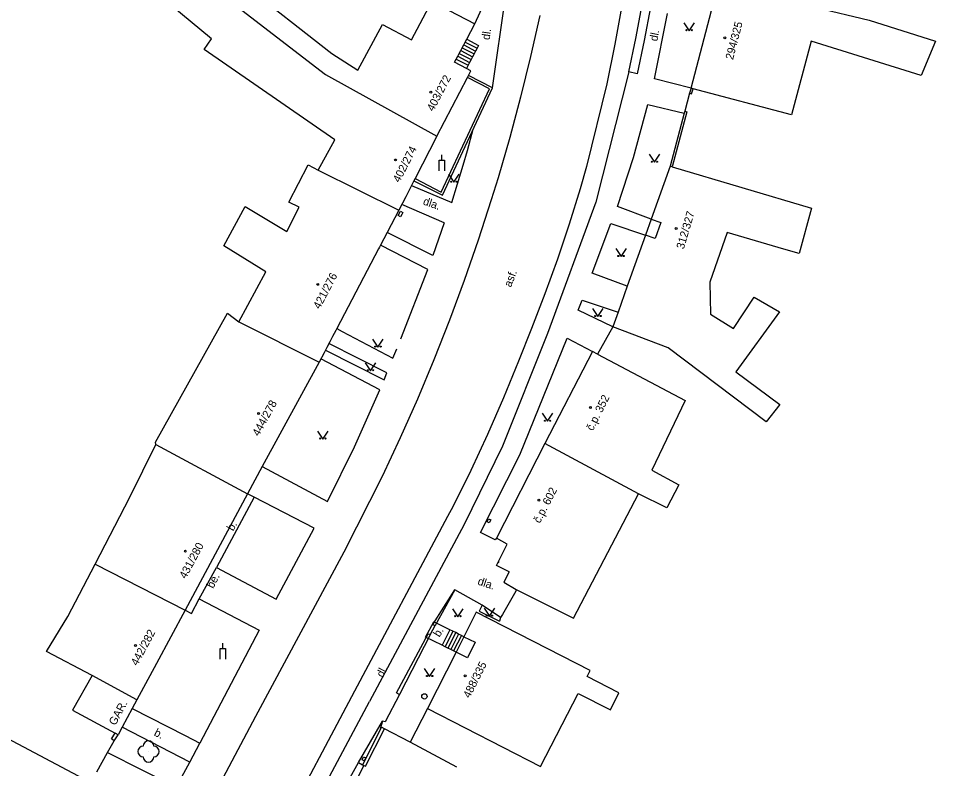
# Model space of a CAD drawing. Extents: x -577457 to -568404, y -1208466 to -1201387.
# Drawn here: x -568911.7 to -568825.8, y -1204266 to -1204195.7 of the extents above; entities that cross this region are included whole.
import ezdxf

# ---------------------------------------------------------------- set-up
doc = ezdxf.new("R2010")
doc.units = 0
for name, color, linetype in [('BUDOVY_MĚŘ', 7, 'Continuous'), ('BUDOVY_NEMĚŘ', 7, 'Continuous'), ('OBVOD_PILÍŘE', 7, 'Continuous'), ('POMOC_POPIS', 7, 'Continuous'), ('ROZHRANÍ_PLOCH', 7, 'Continuous'), ('ZELEŇ', 7, 'Continuous'), ('ZN_BUDOV', 7, 'Continuous'), ('ZN_DOPLŇKOVÉ', 7, 'Continuous'), ('ZN_KULTUR', 7, 'Continuous'), ('Č_POPIS_ORIENT', 7, 'Continuous')]:
    doc.layers.add(name, color=color, linetype=linetype)

msp = doc.modelspace()

# ---------------------------------------------------------------- linework, layer by layer
at = {"layer": 'BUDOVY_MĚŘ'}
for points in [[(-568848.71, -1204202.25), (-568846.12, -1204192.3)], [(-568869.73, -1204197.65), (-568868.98, -1204196.22)], [(-568870, -1204198.18), (-568869.86, -1204197.91)], [(-568869.86, -1204197.91), (-568869.73, -1204197.65)], [(-568870.56, -1204199.24), (-568870.42, -1204198.98)], [(-568870.42, -1204198.98), (-568870.28, -1204198.71)], [(-568870.28, -1204198.71), (-568870.14, -1204198.45)], [(-568870.14, -1204198.45), (-568870, -1204198.18)], [(-568869.74, -1204200.4), (-568870.86, -1204199.81), (-568870.7, -1204199.51)], [(-568870.7, -1204199.51), (-568870.56, -1204199.24)], [(-568869.56, -1204201.04), (-568869.33, -1204200.61), (-568869.74, -1204200.4)], [(-568872.53, -1204206.74), (-568869.66, -1204201.24)], [(-568869.66, -1204201.24), (-568869.56, -1204201.04)], [(-568848.52, -1204202.3), (-568848.71, -1204202.25)], [(-568872.53, -1204206.74), (-568874.57, -1204210.72)], [(-568850.66, -1204209.54), (-568852.44, -1204214.51)], [(-568850.47, -1204209.61), (-568850.66, -1204209.54)], [(-568874.67, -1204210.92), (-568874.9, -1204211.36)], [(-568874.57, -1204210.72), (-568874.67, -1204210.92)], [(-568874.9, -1204211.36), (-568875.43, -1204212.41)], [(-568875.43, -1204212.41), (-568876.09, -1204213.69)], [(-568876.09, -1204213.69), (-568877.18, -1204215.76)], [(-568852.44, -1204214.51), (-568852.97, -1204216.01)], [(-568852.44, -1204214.51), (-568851.54, -1204214.83), (-568852.08, -1204216.33), (-568852.97, -1204216.01)], [(-568877.18, -1204215.76), (-568877.81, -1204216.96)], [(-568852.97, -1204216.01), (-568854.68, -1204220.81)], [(-568877.81, -1204216.96), (-568877.9, -1204217.13)], [(-568877.99, -1204217.31), (-568881.9, -1204224.78)], [(-568877.9, -1204217.13), (-568877.99, -1204217.31)], [(-568854.68, -1204220.81), (-568855.55, -1204223.25)], [(-568855.55, -1204223.25), (-568856.04, -1204224.61)], [(-568881.9, -1204224.78), (-568881.99, -1204224.95)], [(-568882.29, -1204225.51), (-568882.56, -1204226.03)], [(-568881.99, -1204224.95), (-568882.29, -1204225.51)], [(-568882.56, -1204226.03), (-568882.82, -1204226.54)], [(-568883.09, -1204227.05), (-568883.55, -1204227.92)], [(-568882.82, -1204226.54), (-568883.09, -1204227.05)], [(-568857.93, -1204226.94), (-568862.4, -1204235.55)], [(-568857.48, -1204227.16), (-568857.93, -1204226.94)], [(-568883.55, -1204227.92), (-568888.88, -1204237.7)], [(-568862.4, -1204235.55), (-568866.94, -1204244.43)], [(-568888.88, -1204237.7), (-568890.27, -1204240.26)], [(-568890.27, -1204240.26), (-568896.11, -1204251.18)], [(-568865.94, -1204244.99), (-568866.94, -1204244.43)], [(-568866.95, -1204246.98), (-568865.94, -1204244.99)], [(-568865.75, -1204247.58), (-568866.95, -1204246.98)], [(-568866.72, -1204246.65), (-568866.78, -1204246.77)], [(-568865.75, -1204247.58), (-568866.24, -1204248.55)], [(-568866.24, -1204248.55), (-568865.08, -1204249.24)], [(-568896.11, -1204251.18), (-568898.79, -1204256.16)], [(-568868.84, -1204251.35), (-568870, -1204253.66)], [(-568870, -1204253.66), (-568868.93, -1204254.19), (-568869.65, -1204255.64), (-568870.73, -1204255.1)], [(-568870, -1204253.66), (-568870.73, -1204255.1)], [(-568870.73, -1204255.1), (-568873.39, -1204260.4)], [(-568898.79, -1204256.16), (-568900.63, -1204259.59)], [(-568900.63, -1204259.59), (-568901.07, -1204260.4)], [(-568901.07, -1204260.4), (-568902.01, -1204262.15)], [(-568902.01, -1204262.15), (-568902.39, -1204262.86)], [(-568902.39, -1204262.86), (-568902.65, -1204262.72)]]:
    msp.add_lwpolyline(points, dxfattribs=at)
at = {"layer": 'BUDOVY_NEMĚŘ'}
for points in [[(-568883.64, -1204209.91), (-568882.08, -1204207.07), (-568894.33, -1204198.62), (-568893.64, -1204197.62), (-568905.07, -1204188.12), (-568902.99, -1204185.45), (-568896.69, -1204190.35), (-568892.01, -1204194), (-568882.96, -1204200.94), (-568872.53, -1204206.74)], [(-568892.01, -1204194), (-568890.82, -1204192.33), (-568882.37, -1204198.99), (-568879.93, -1204200.55), (-568877.61, -1204196.28), (-568874.91, -1204197.7), (-568873.01, -1204194.12), (-568868.98, -1204196.22)], [(-568836.99, -1204194.68), (-568832.03, -1204195.87), (-568825.79, -1204197.84), (-568827.15, -1204201.06), (-568837.45, -1204197.83), (-568839.31, -1204204.74), (-568848.52, -1204202.3)], [(-568891.08, -1204224.13), (-568888.56, -1204219.47), (-568892.49, -1204217.03), (-568890.47, -1204213.33), (-568886.58, -1204215.68), (-568885.43, -1204213.4), (-568886.38, -1204212.91), (-568884.58, -1204209.42), (-568883.64, -1204209.91), (-568876.09, -1204213.69)], [(-568850.47, -1204209.61), (-568837.41, -1204213.5), (-568838.58, -1204217.74), (-568840, -1204217.32), (-568845.32, -1204215.76), (-568846.96, -1204220.41), (-568846.87, -1204223.42), (-568844.73, -1204224.77), (-568842.79, -1204221.83), (-568840.43, -1204223.21), (-568844.52, -1204228.83), (-568840.39, -1204231.89), (-568841.66, -1204233.53), (-568850.84, -1204226.59), (-568856.04, -1204224.61)], [(-568898.85, -1204235.64), (-568898.87, -1204235.42), (-568892.14, -1204223.32), (-568891.08, -1204224.13), (-568883.55, -1204227.92)], [(-568857.48, -1204227.16), (-568849.26, -1204231.52), (-568852.37, -1204238.06), (-568849.84, -1204239.43), (-568850.98, -1204241.59), (-568853.64, -1204240.28)], [(-568904.54, -1204246.87), (-568901.28, -1204240.58), (-568898.85, -1204235.64), (-568890.27, -1204240.26)], [(-568853.64, -1204240.28), (-568862.4, -1204235.55)], [(-568859.72, -1204251.94), (-568853.64, -1204240.28)], [(-568904.83, -1204257.31), (-568909.1, -1204255.04), (-568907.09, -1204251.77), (-568904.54, -1204246.87), (-568896.11, -1204251.18)], [(-568865.08, -1204249.24), (-568859.72, -1204251.94)], [(-568873.39, -1204260.4), (-568862.8, -1204265.84), (-568859.27, -1204258.99), (-568856.27, -1204260.53), (-568855.47, -1204258.94), (-568858.45, -1204257.4), (-568858.15, -1204256.83), (-568868.84, -1204251.35)], [(-568900.63, -1204259.59), (-568904.83, -1204257.31), (-568906.67, -1204260.55), (-568902.65, -1204262.72)], [(-568919.63, -1204274.47), (-568913.32, -1204262.9), (-568905.13, -1204267.24)]]:
    msp.add_lwpolyline(points, dxfattribs=at)
at = {"layer": 'OBVOD_PILÍŘE'}
for points in [[(-568875.82, -1204214.09), (-568875.93, -1204214.3), (-568876.15, -1204214.18), (-568875.93, -1204213.77), (-568875.71, -1204213.88), (-568875.82, -1204214.09)], [(-568867.74, -1204242.74), (-568867.67, -1204242.6), (-568867.47, -1204242.7), (-568867.62, -1204242.98), (-568867.81, -1204242.88), (-568867.74, -1204242.74)], [(-568879.46, -1204265.06), (-568879.39, -1204264.92), (-568879.19, -1204265.02), (-568879.34, -1204265.3), (-568879.53, -1204265.2), (-568879.46, -1204265.06)]]:
    msp.add_lwpolyline(points, dxfattribs=at)
at = {"layer": 'ROZHRANÍ_PLOCH'}
for points in [[(-568852.84, -1204191.52), (-568851.72, -1204182.22), (-568850.93, -1204182.32), (-568852.05, -1204191.64), (-568852.52, -1204194.63), (-568853.1, -1204197.76), (-568853.75, -1204200.88), (-568854.53, -1204200.71), (-568853.88, -1204197.58), (-568853.3, -1204194.43), (-568852.84, -1204191.52)], [(-568867.3, -1204202.19), (-568866.1, -1204193.68)], [(-568855.15, -1204194.34), (-568855.84, -1204198.1)], [(-568862.89, -1204195.42), (-568863.75, -1204199.26)], [(-568852.14, -1204201.36), (-568850.92, -1204195.24)], [(-568869.86, -1204197.91), (-568868.75, -1204198.5)], [(-568869.73, -1204197.65), (-568868.61, -1204198.23), (-568868.75, -1204198.5)], [(-568855.84, -1204198.1), (-568856.61, -1204201.84)], [(-568870.42, -1204198.98), (-568869.31, -1204199.56)], [(-568870.28, -1204198.71), (-568869.17, -1204199.29)], [(-568870.14, -1204198.45), (-568869.03, -1204199.03)], [(-568870, -1204198.18), (-568868.89, -1204198.76)], [(-568868.89, -1204198.76), (-568869.03, -1204199.03)], [(-568868.75, -1204198.5), (-568868.89, -1204198.76)], [(-568870.7, -1204199.51), (-568869.58, -1204200.09)], [(-568870.56, -1204199.24), (-568869.45, -1204199.83)], [(-568869.45, -1204199.83), (-568869.58, -1204200.09)], [(-568869.31, -1204199.56), (-568869.45, -1204199.83)], [(-568869.17, -1204199.29), (-568869.31, -1204199.56)], [(-568869.03, -1204199.03), (-568869.17, -1204199.29)], [(-568863.75, -1204199.26), (-568864.68, -1204203.07)], [(-568869.58, -1204200.09), (-568869.74, -1204200.4)], [(-568854.53, -1204200.71), (-568857.63, -1204212.94)], [(-568848.71, -1204202.25), (-568852.14, -1204201.36)], [(-568856.61, -1204201.84), (-568858.49, -1204209.59)], [(-568864.68, -1204203.07), (-568865.69, -1204206.87)], [(-568852.44, -1204214.51), (-568855.61, -1204213.34), (-568854.11, -1204208.74), (-568852.75, -1204203.77), (-568849.34, -1204204.59)], [(-568869.65, -1204208.08), (-568869.12, -1204206.09)], [(-568865.69, -1204206.87), (-568866.78, -1204210.64)], [(-568870.05, -1204209.47), (-568869.65, -1204208.08)], [(-568871.12, -1204212.97), (-568870.05, -1204209.47)], [(-568858.49, -1204209.59), (-568859.09, -1204211.66)], [(-568866.78, -1204210.64), (-568867.42, -1204212.7)], [(-568874.9, -1204211.36), (-568871.12, -1204212.97)], [(-568859.09, -1204211.66), (-568860.12, -1204214.98)], [(-568867.42, -1204212.7), (-568868.65, -1204216.49)], [(-568871.83, -1204214.87), (-568875.8, -1204213.13)], [(-568857.63, -1204212.94), (-568862.15, -1204225.24)], [(-568871.83, -1204214.87), (-568872.9, -1204217.93)], [(-568860.12, -1204214.98), (-568861.22, -1204218.27)], [(-568854.68, -1204220.81), (-568857.97, -1204219.59), (-568856.21, -1204214.91), (-568852.97, -1204216.01)], [(-568872.9, -1204217.93), (-568877.18, -1204215.76)], [(-568873.36, -1204219.25), (-568877.81, -1204216.96)], [(-568868.65, -1204216.49), (-568869.97, -1204220.26)], [(-568861.22, -1204218.27), (-568862.4, -1204221.53)], [(-568875.91, -1204225.73), (-568873.36, -1204219.25)], [(-568869.97, -1204220.26), (-568871.35, -1204223.99)], [(-568862.4, -1204221.53), (-568863.66, -1204224.77)], [(-568856.04, -1204224.61), (-568859.29, -1204223.04), (-568858.92, -1204222.1), (-568855.55, -1204223.25)], [(-568881.9, -1204224.78), (-568881.4, -1204225.04)], [(-568871.35, -1204223.99), (-568872.81, -1204227.7)], [(-568863.66, -1204224.77), (-568864.86, -1204227.84)], [(-568881.4, -1204225.04), (-568876.65, -1204227.55)], [(-568862.15, -1204225.24), (-568866.38, -1204235.81)], [(-568877.2, -1204228.93), (-568882.64, -1204226.19)], [(-568864.76, -1204236.6), (-568860.33, -1204225.66)], [(-568860.33, -1204225.66), (-568857.93, -1204226.94)], [(-568882.96, -1204226.81), (-568877.47, -1204229.59)], [(-568876.65, -1204227.55), (-568876.28, -1204226.68)], [(-568877.87, -1204230.52), (-568883.39, -1204227.62)], [(-568872.81, -1204227.7), (-568874.35, -1204231.38)], [(-568864.86, -1204227.84), (-568866.28, -1204231.28)], [(-568877.47, -1204229.59), (-568877.2, -1204228.93)], [(-568880.25, -1204235.87), (-568877.87, -1204230.52)], [(-568874.35, -1204231.38), (-568875.96, -1204235.03)], [(-568866.28, -1204231.28), (-568867.78, -1204234.7)], [(-568875.96, -1204235.03), (-568877.64, -1204238.64)], [(-568867.78, -1204234.7), (-568869.35, -1204238.08)], [(-568882.76, -1204240.99), (-568880.25, -1204235.87)], [(-568866.38, -1204235.81), (-568869.98, -1204243.15)], [(-568868.45, -1204243.9), (-568864.76, -1204236.6)], [(-568888.88, -1204237.7), (-568882.76, -1204240.99)], [(-568869.35, -1204238.08), (-568870.99, -1204241.42)], [(-568877.64, -1204238.64), (-568881.23, -1204245.73)], [(-568893.17, -1204247.16), (-568887.57, -1204250.14), (-568884.02, -1204243.49), (-568889.65, -1204240.58)], [(-568889.65, -1204240.58), (-568893.17, -1204247.16)], [(-568889.65, -1204240.58), (-568890.27, -1204240.26)], [(-568870.99, -1204241.42), (-568871.54, -1204242.39)], [(-568871.54, -1204242.39), (-568880.24, -1204258.77)], [(-568869.98, -1204243.15), (-568878.83, -1204259.75)], [(-568867.05, -1204244.58), (-568868.45, -1204243.9)], [(-568866.94, -1204244.43), (-568867.05, -1204244.58)], [(-568881.23, -1204245.73), (-568889.51, -1204261.16)], [(-568894.79, -1204250.12), (-568893.17, -1204247.16)], [(-568872.89, -1204252.51), (-568870.83, -1204249.28)], [(-568896.11, -1204251.18), (-568895.51, -1204251.49), (-568894.79, -1204250.12)], [(-568894.79, -1204250.12), (-568889.16, -1204253.06), (-568894.74, -1204263.63)], [(-568866.55, -1204251.86), (-568868.27, -1204250.71)], [(-568873.6, -1204253.7), (-568872.82, -1204252.26)], [(-568871.3, -1204253.01), (-568872.82, -1204252.26)], [(-568872.89, -1204252.51), (-568872.68, -1204252.62)], [(-568871.3, -1204253.01), (-568872.03, -1204254.47)], [(-568871.03, -1204253.15), (-568871.3, -1204253.01)], [(-568876.31, -1204258.93), (-568873.34, -1204253.39)], [(-568872.03, -1204254.47), (-568873.6, -1204253.7)], [(-568873.34, -1204253.39), (-568873.12, -1204253.42)], [(-568871.03, -1204253.15), (-568871.76, -1204254.6)], [(-568870.76, -1204253.28), (-568871.49, -1204254.73)], [(-568870.49, -1204253.41), (-568871.22, -1204254.86)], [(-568870.76, -1204253.28), (-568871.03, -1204253.15)], [(-568870.22, -1204253.55), (-568870.95, -1204254.99)], [(-568870.49, -1204253.41), (-568870.76, -1204253.28)], [(-568870.22, -1204253.55), (-568870.49, -1204253.41)], [(-568870, -1204253.66), (-568870.22, -1204253.55)], [(-568871.76, -1204254.6), (-568872.03, -1204254.47)], [(-568871.49, -1204254.73), (-568871.76, -1204254.6)], [(-568871.22, -1204254.86), (-568871.49, -1204254.73)], [(-568870.95, -1204254.99), (-568871.22, -1204254.86)], [(-568870.73, -1204255.1), (-568870.95, -1204254.99)], [(-568880.24, -1204258.77), (-568894.54, -1204285.77)], [(-568876.31, -1204258.93), (-568876.01, -1204259.09)], [(-568893.08, -1204286.46), (-568878.83, -1204259.75)], [(-568901.07, -1204260.4), (-568896.12, -1204262.93), (-568894.74, -1204263.63)], [(-568889.51, -1204261.16), (-568901.2, -1204283.21)], [(-568879.86, -1204265.46), (-568877.63, -1204261.58)], [(-568877.37, -1204261.66), (-568877.63, -1204261.58)], [(-568895.67, -1204265.43), (-568902.01, -1204262.15)], [(-568895.67, -1204265.43), (-568894.74, -1204263.63)], [(-568903.37, -1204264.51), (-568896.96, -1204267.78), (-568895.67, -1204265.43)], [(-568882.47, -1204270.1), (-568879.86, -1204265.46)], [(-568879.86, -1204265.46), (-568879.49, -1204265.67)]]:
    msp.add_lwpolyline(points, dxfattribs=at)
at = {"layer": 'ZELEŇ'}
msp.add_circle((-568899.54, -1204264.43), 0.0005, dxfattribs=at)
for centre, start, end in [((-568899.54, -1204263.93), 0, 179.99999), ((-568900.04, -1204264.43), 89.99999, 269.99999), ((-568899.04, -1204264.43), 270, 89.99999), ((-568899.54, -1204264.93), 179.99999, 359.99999)]:
    msp.add_arc(centre, 0.5, start, end, dxfattribs=at)
at = {"layer": 'ZN_BUDOV'}
for centre in [(-568845.54, -1204197.51), (-568873.08, -1204202.62), (-568876.39, -1204208.97), (-568850.1, -1204215.39), (-568883.69, -1204220.63), (-568858.14, -1204232.18), (-568889.22, -1204232.73), (-568862.96, -1204240.86), (-568896.09, -1204245.65), (-568900.76, -1204254.48), (-568869.88, -1204257.34)]:
    msp.add_circle(centre, 0.0875, dxfattribs=at)
at = {"layer": 'ZN_DOPLŇKOVÉ'}
for p, q in [((-568872.05, -1204208.98), (-568872.05, -1204208.48)), ((-568892.57, -1204254.78), (-568892.57, -1204254.28))]:
    msp.add_line(p, q, dxfattribs=at)
for points in [[(-568868.98, -1204196.22), (-568867.77, -1204193.57)], [(-568874.57, -1204210.72), (-568872.11, -1204211.98), (-568867.59, -1204202.29), (-568869.66, -1204201.24)], [(-568867.3, -1204202.19), (-568869.56, -1204201.04)], [(-568874.67, -1204210.92), (-568872.01, -1204212.28), (-568867.3, -1204202.19)], [(-568848.71, -1204202.25), (-568848.85, -1204202.72)], [(-568848.85, -1204202.72), (-568848.66, -1204202.78), (-568848.52, -1204202.3)], [(-568848.85, -1204202.72), (-568849.29, -1204204.4)], [(-568849.34, -1204204.59), (-568850.66, -1204209.54)], [(-568849.29, -1204204.4), (-568849.1, -1204204.45), (-568850.47, -1204209.61)], [(-568849.29, -1204204.4), (-568849.34, -1204204.59)], [(-568872.3, -1204209.98), (-568872.3, -1204208.98), (-568871.8, -1204208.98), (-568871.8, -1204209.98)], [(-568856.04, -1204224.61), (-568857.48, -1204227.16)], [(-568870.83, -1204249.28), (-568872.68, -1204252.62)], [(-568868.27, -1204250.71), (-568870.83, -1204249.28)], [(-568865.14, -1204249.4), (-568866.37, -1204251.57)], [(-568865.08, -1204249.24), (-568865.14, -1204249.4)], [(-568868.27, -1204250.71), (-568868.55, -1204251.27)], [(-568868.55, -1204251.27), (-568866.66, -1204252.22)], [(-568866.55, -1204251.86), (-568866.66, -1204252.22)], [(-568866.37, -1204251.57), (-568866.55, -1204251.86)], [(-568873.12, -1204253.42), (-568872.68, -1204252.62)], [(-568873.12, -1204253.42), (-568876.01, -1204259.09)], [(-568892.82, -1204255.78), (-568892.82, -1204254.78), (-568892.32, -1204254.78), (-568892.32, -1204255.78)], [(-568876.01, -1204259.09), (-568877.37, -1204261.66)], [(-568873.39, -1204260.4), (-568875.03, -1204263.56)], [(-568877.63, -1204261.58), (-568877.85, -1204262.31)], [(-568877.44, -1204262.29), (-568877.7, -1204262.15), (-568879.49, -1204265.67), (-568879.36, -1204265.74)], [(-568879.36, -1204265.74), (-568879.22, -1204265.81), (-568877.44, -1204262.29)], [(-568875.03, -1204263.56), (-568877.44, -1204262.29)], [(-568903.37, -1204264.51), (-568902.77, -1204263.42)], [(-568902.77, -1204263.42), (-568903.02, -1204263.25), (-568902.65, -1204262.72)], [(-568902.77, -1204263.42), (-568902.39, -1204262.86)], [(-568870.64, -1204265.88), (-568875.03, -1204263.56)], [(-568904.37, -1204266.32), (-568903.37, -1204264.51)], [(-568879.36, -1204265.74), (-568881.13, -1204269.15), (-568881.74, -1204270.36)]]:
    msp.add_lwpolyline(points, dxfattribs=at)
for radius in [0.25, 0.0005]:
    msp.add_circle((-568873.69, -1204259.26), radius, dxfattribs=at)
at = {"layer": 'ZN_KULTUR'}
for points in [[(-568849.38, -1204196.1), (-568848.88, -1204196.85), (-568848.38, -1204196.1)], [(-568852.64, -1204208.44), (-568852.14, -1204209.19), (-568851.64, -1204208.44)], [(-568871.43, -1204210.31), (-568870.93, -1204211.06), (-568870.43, -1204210.31)], [(-568855.77, -1204217.27), (-568855.27, -1204218.02), (-568854.77, -1204217.27)], [(-568857.93, -1204222.9), (-568857.43, -1204223.65), (-568856.93, -1204222.9)], [(-568878.54, -1204225.76), (-568878.04, -1204226.51), (-568877.54, -1204225.76)], [(-568879.24, -1204227.98), (-568878.74, -1204228.73), (-568878.24, -1204227.98)], [(-568862.65, -1204232.72), (-568862.15, -1204233.47), (-568861.65, -1204232.72)], [(-568883.71, -1204234.38), (-568883.21, -1204235.13), (-568882.71, -1204234.38)], [(-568871.07, -1204251.04), (-568870.57, -1204251.79), (-568870.07, -1204251.04)], [(-568868.1, -1204250.99), (-568867.6, -1204251.74), (-568867.1, -1204250.99)], [(-568873.7, -1204256.65), (-568873.2, -1204257.4), (-568872.7, -1204256.65)]]:
    msp.add_lwpolyline(points, dxfattribs=at)
for centre in [(-568849.13, -1204196.8), (-568848.63, -1204196.8), (-568852.39, -1204209.14), (-568851.89, -1204209.14), (-568871.18, -1204211.01), (-568870.68, -1204211.01), (-568855.52, -1204217.97), (-568855.02, -1204217.97), (-568857.68, -1204223.6), (-568857.18, -1204223.6), (-568878.29, -1204226.46), (-568877.79, -1204226.46), (-568878.99, -1204228.68), (-568878.49, -1204228.68), (-568862.4, -1204233.42), (-568861.9, -1204233.42), (-568883.46, -1204235.08), (-568882.96, -1204235.08), (-568870.82, -1204251.74), (-568870.32, -1204251.74), (-568867.85, -1204251.69), (-568867.35, -1204251.69), (-568873.45, -1204257.35), (-568872.95, -1204257.35)]:
    msp.add_circle(centre, 0.05, dxfattribs=at)

# ---------------------------------------------------------------- texts
at = {"layer": 'POMOC_POPIS'}
for s, rotation, p in [('dl.', 81.96998, (-568867.59, -1204197.75)), ('dl.', 78.73002, (-568851.88, -1204197.88)), ('dla.', 340.70001, (-568873.88, -1204213.13)), ('asf.', 68.75001, (-568865.58, -1204220.95)), ('b.', 59.25002, (-568891.62, -1204243.81)), ('be.', 62.18998, (-568893.49, -1204249.2)), ('dla.', 341.56999, (-568868.76, -1204248.76)), ('b.', 58.56998, (-568872.28, -1204253.76)), ('dl.', 63.31, (-568877.58, -1204257.54)), ('GAR.', 61.73998, (-568902.65, -1204262.04)), ('b.', 332.65001, (-568899.09, -1204262.89))]:
    msp.add_text(s, height=0.75, rotation=rotation, dxfattribs=at).set_placement(p)
at = {"layer": 'Č_POPIS_ORIENT'}
for s, rotation, p in [('294/325', 75.41001, (-568844.78, -1204199.62)), ('403/272', 62.43, (-568872.85, -1204204.47)), ('402/274', 62.88, (-568876.03, -1204211.14)), ('312/327', 73.57998, (-568849.39, -1204217.38)), ('421/276', 62.33002, (-568883.5, -1204223.01)), ('444/278', 61.43001, (-568889.21, -1204234.93)), ('č.p. 352', 63.61997, (-568857.91, -1204234.42)), ('č.p. 602', 62.78002, (-568862.87, -1204243.08)), ('431/280', 61.86002, (-568896.05, -1204248.29)), ('442/282', 61.73998, (-568900.59, -1204256.44)), ('488/335', 63.31, (-568869.45, -1204259.48))]:
    msp.add_text(s, height=0.75, rotation=rotation, dxfattribs=at).set_placement(p)

doc.saveas('drawing.dxf')
